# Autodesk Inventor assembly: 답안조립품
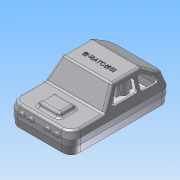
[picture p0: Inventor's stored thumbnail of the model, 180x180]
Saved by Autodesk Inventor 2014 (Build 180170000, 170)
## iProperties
Created: 2015-05
Part Number: 답안조립품
Document SubType Name: Assembly
Designer: Administrator
Author: Administrator
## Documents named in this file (3)
- C:\Documents and Settings\Administrator\바탕 화면\450508V1024\답안조립품.iam
- C:\Documents and Settings\Administrator\바탕 화면\450508V1024\450508V1024\본체.ipt
- C:\Documents and Settings\Administrator\바탕 화면\450508V1024\450508V1024\커버.ipt
